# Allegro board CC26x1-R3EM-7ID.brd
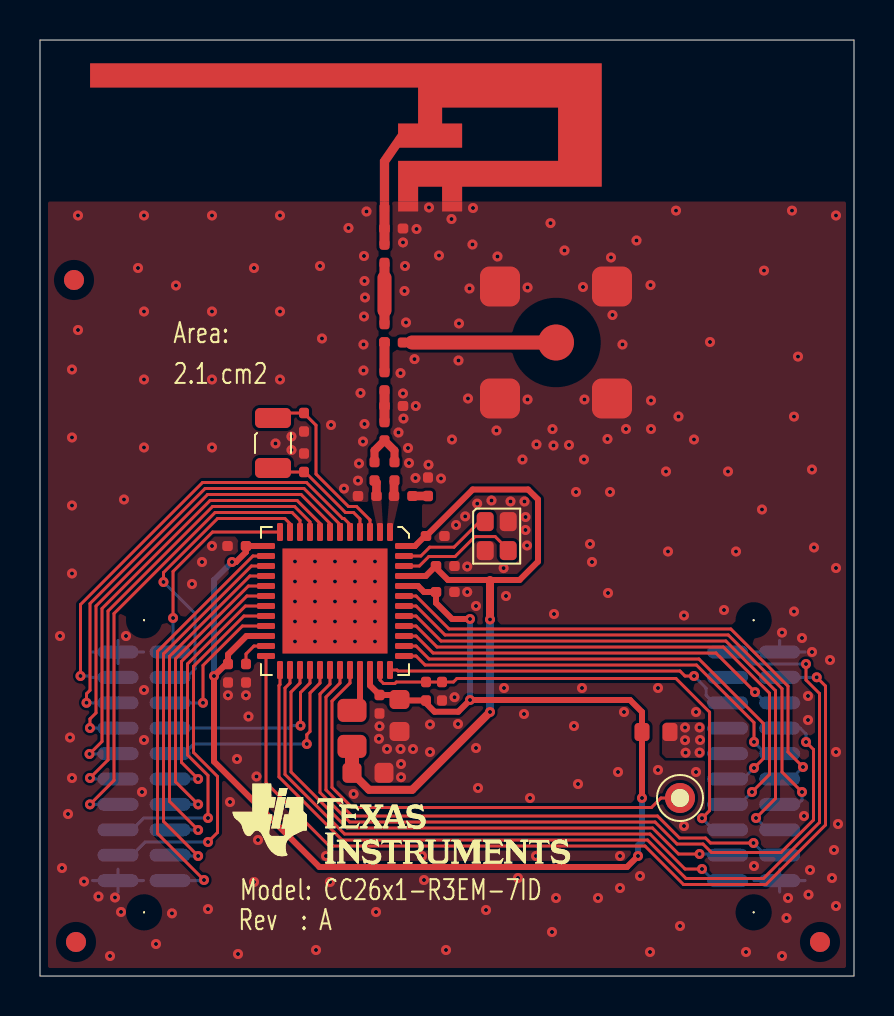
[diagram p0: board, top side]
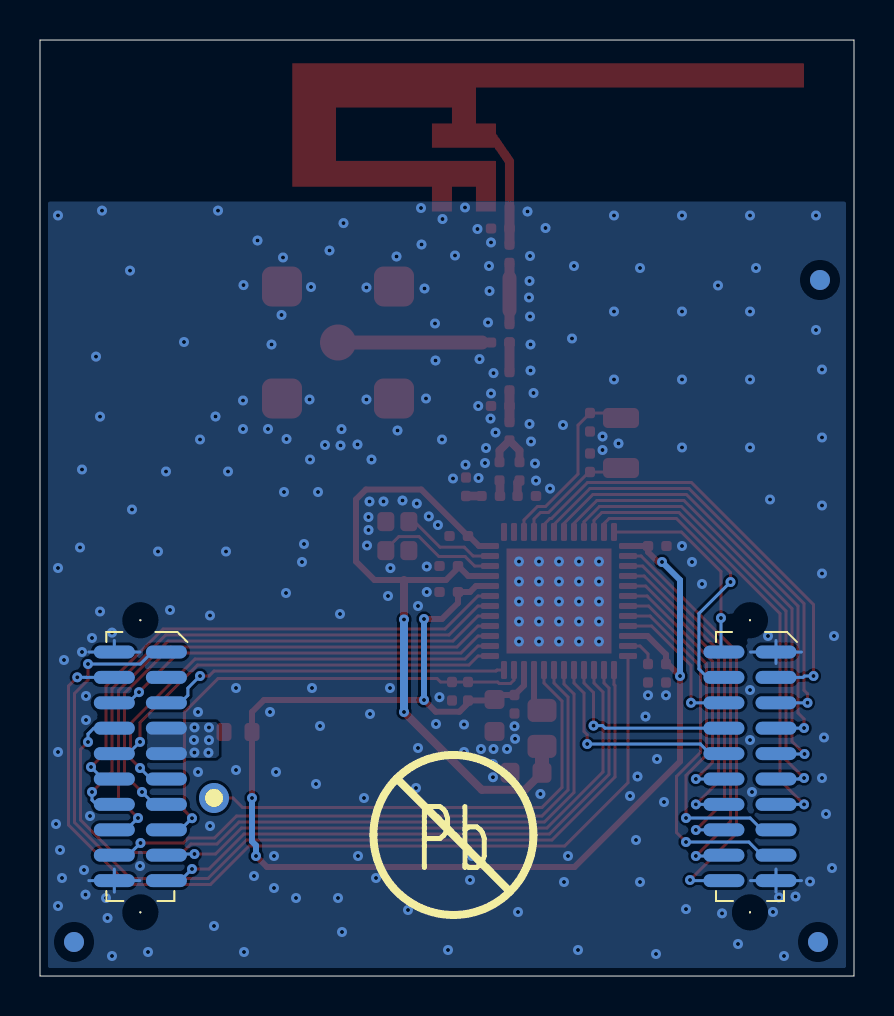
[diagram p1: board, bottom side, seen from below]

Outline 40.7 x 46.8 mm; copper layers: TOP, BOTTOM. Coordinates in mm from the lower left corner of the outline.
Outline path: 0,46.8 0,0 40.7,0 40.7,46.8 0,46.8

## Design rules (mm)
constraint set DEFAULT: min track width 0.15

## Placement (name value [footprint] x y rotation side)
A1  2.4GHz  [ANTENNA_DN007AN]  17.23 38.48 0 top
C3  0.1uF  [CAPC1005X60B2N]  10.3 21.5 180 top
C4  0.1uF  [CAPC1005X60B2N]  9.4 15.6 270 top
C5  0.1uF  [CAPC1005X60B2N]  19.8 19.2 0 top
C6  22uF  [CAPC1608X100A2N]  17.98 13.83 270 top
C7  0.1uF  [CAPC1005X60B2N]  16.98 14.05 270 top
C8  22uF  [CAPC1608X100A2N]  15.6 10.16 0 top
C9  0.1uF  [CAPC1005X60B2N]  19.8 20.5 0 top
C11  1pF  [CAPC1005X60B2N]  17.73 24.78 90 top
C13  1pF  [CAPC1005X60B2N]  18.15 28.5 180 top
C14  12pF  [CAPC1005X60B2N]  17.23 31.67 90 top
C15  DNM_0402  [CAPC1005X60B2N]  17.23 37.38 0 top
C16  0.1uF  [CAPC1005X60B2N]  19.3 22 0 top
C17  12pF  [CAPC1005X60B2N]  13.2 28.15 270 top
C18  12pF  [CAPC1005X60B2N]  13.2 25.2 90 top
C19  1uF  [CAPC1005X60B2N]  10.3 15.6 270 top
C20  0.1uF  [CAPC1005X60B2N]  20.1 14.7 270 top
C21  1pF  [CAPC1005X60B2N]  15.9 24 0 top
C24  12pF  [CAPC1005X60B2N]  18.15 31.67 180 top
C31  12pF  [CAPC1005X60B2N]  19.4 24 90 top
DIO22  TP_CIR_1.5mm_HOLE_0.9mm  [TP150_90H]  32 8.9 0 top
FIDU1  FIDU_1MM  [FID100X115B]  1.8 1.7 0 top
FIDU2  FIDU_1MM  [FID100X115B]  39 1.7 0 top
FIDU3  FIDU_1MM  [FID100X115B]  1.7 34.8 0 top
FIDU4  FIDU_1MM  [FID100X115B]  1.8 1.7 180 bottom
FIDU5  FIDU_1MM  [FID100X115B]  39 1.7 180 bottom
FIDU6  FIDU_1MM  [FID100X115B]  1.7 34.8 180 bottom
FL1  BLM18HE152SN1  [FIL_BLM18HE152SN1DN]  30.1 12.2 0 top
J1  SMA-10V21-TGG  [HUSTSAN_SMA10V21TGGAN]  25.8 31.67 0 top
L1  6.8uH  [INDC2012X150A2N]  15.6 13.28 270 top
L11  2.4nH  [INDC1005X60D2N]  17.7 24 0 top
L12  2nH  [INDC1005X60D2N]  17.23 26.78 90 top
L13  2nH  [INDC1005X60D2N]  17.23 29.28 90 top
L21  2.4nH  [INDC1005X60D2N]  16.73 24.78 90 top
LBL1  NON_COMPONENT_LABEL_8mm  [LABEL_PB-FREE_8MM_A2N]  24.24 2.84 180 bottom
LBL2  TI_LOGO  [TI_LOGO_1]  10.62 9.62 0 top
NOREF  -  []  0 40.29 0 top
NOREF#2  -  []  29.02 0 90 top
P1  SFM-110-02-S-D-A-K  [SAMTEC_SFM11002AN]  3.9 16.2 0 bottom
P2  SFM-110-02-S-D-A-K  [SAMTEC_SFM11002AN]  34.38 16.2 0 bottom
R1  100k  [RESC1005X40B2N]  19.3 14.7 270 top
R12  0  [RESC1005X40B2N]  17.23 36.58 270 top
U1  CC2651R31T0RGZR  [QFNFC50P700X700X100-49A2N]  17.5 22.2 180 top
Y1  32.768kHz  [XTAL_TZ1166C_A2N]  11.65 27.9 270 top
Y2  48MHz  [OSCCC200X160X50-4A2N]  22.26 22.72 270 top

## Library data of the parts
A1 = ANTENNA_DN007
C3-C5 C7 C9 C11 C13 C14 C16-C21 C24 C31 = CAPACITOR: User Part Number: #PN
C6 C8 = CAPACITOR: User Part Number: #PN; alternate symbols: (CAPC1608X100A2L,CAPC1608X100A2M)
C15 = CAPACITOR_CAPC1005X60B2N_DISC_2: User Part Number: #PN
DIO22 = TEST_POINT
FIDU1-FIDU6 = FIDMARK
FL1 = FILTER_2PIN: alternate symbols: (FIL_BLM18HE152SN1DL,FIL_BLM18HE152SN1DM)
J1 = CONN_COAX_1+4: alternate symbols: (HUSTSAN_SMA10V21TGGL,HUSTSAN_SMA10V21TGGM)
L1 = INDUCTOR: User Part Number: #PN; alternate symbols: (INDC2012X150A2L,INDC2012X150A2M)
L11-L13 L21 = INDUCTOR_HOR_1_2: User Part Number: #PN
LBL1 = LABEL_Pb-free_V1: User Part Number: #PN
LBL2 = TI_LOGO_V1
P1 P2 = CONN_HEADER_2X10_P_S: alternate symbols: (SAMTEC_SFM11002AL,SAMTEC_SFM11002AM)
R1 R12 = RESISTOR: User Part Number: #PN
U1 = IC_RF_CC2651R1F32_VQFN48: User Part Number: #PN; alternate symbols: (QFNFC50P700X700X100-49A2L,QFNFC50P700X700X100-49A2M)
Y1 = XTAL: User Part Number: #PN; alternate symbols: (XTAL_TZ1166C_A2L,XTAL_TZ1166C_A2M)
Y2 = XTAL_4_V3: User Part Number: #PN; alternate symbols: (OSCCC200X160X50-4A2L,OSCCC200X160X50-4A2M)

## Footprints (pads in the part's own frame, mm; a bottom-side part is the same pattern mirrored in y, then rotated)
ANTENNA_DN007AN
  rect 0.46x0.5 smd: 1(0,0)
  rect 1x0.5 smd: 2(1.18,0) 3(3.38,0)
CAPC1005X60B2N
  custom 0.125x0.125 smd: 1(0,0) 2(0.924,0)
CAPC1608X100A2N
  custom 0.237x0.237 smd: 1(0,0) 2(1.6,0)
FID100X115B
  round 1 smd: 1(0,0)
FIL_BLM18HE152SN1DN
  custom 0.188x0.188 smd: 1(0,0) 2(1.4,0)
HUSTSAN_SMA10V21TGGAN
  round 1.801 smd: 1(0,0)
  custom 0.5x0.5 smd: 2(-2.8,-2.8) 3(2.8,-2.8) 4(2.8,2.8) 5(-2.8,2.8)
INDC1005X60D2N
  custom 0.125x0.125 smd: 1(0,0) 2(0.924,0)
INDC2012X150A2N
  custom 0.287x0.287 smd: 1(0,0) 2(1.8,0)
OSCCC200X160X50-4A2N
  custom 0.212x0.212 smd: 1(0,0) 2(1.45,0) 3(1.45,1.15) 4(0,1.15)
QFNFC50P700X700X100-49A2N
  custom 0.075x0.075 smd: 1(0,0) 2(0.5,0) 3(1,0) 4(1.5,0) 5(2,0) 6(2.5,0) 7(3,0) 8(3.5,0) 9(4,0) 10(4.5,0) 11(5,0) 12(5.5,0) 13(6.2,0.7) 14(6.2,1.2) 15(6.2,1.7) 16(6.2,2.2) 17(6.2,2.7) 18(6.2,3.2) 19(6.2,3.7) 20(6.2,4.2) 21(6.2,4.7) 22(6.2,5.2) 23(6.2,5.7) 24(6.2,6.2) 25(5.5,6.9) 26(5,6.9) 27(4.5,6.9) 28(4,6.9) 29(3.5,6.9) 30(3,6.9) 31(2.5,6.9) 32(2,6.9) 33(1.5,6.9) 34(1,6.9) 35(0.5,6.9) 36(0,6.9) 37(-0.7,6.2) 38(-0.7,5.7) 39(-0.7,5.2) 40(-0.7,4.7) 41(-0.7,4.2) 42(-0.7,3.7) 43(-0.7,3.2) 44(-0.7,2.7) 45(-0.7,2.2) 46(-0.7,1.7) 47(-0.7,1.2) 48(-0.7,0.7)
  rect 5.25x5.25 smd: 49(2.75,3.45)
RESC1005X40B2N
  custom 0.125x0.125 smd: 1(0,0) 2(0.924,0)
SAMTEC_SFM11002AN
  round 0.099 hole 1.501 unplated: (1.302,-1.588) (1.302,13.017)
  oval 2.05x0.65 smd: 1(0,0) 2(2.604,0) 3(0,1.27) 4(2.604,1.27) 5(0,2.54) 6(2.604,2.54) 7(0,3.81) 8(2.604,3.81) 9(0,5.08) 10(2.604,5.08) 11(0,6.35) 12(2.604,6.35) 13(0,7.62) 14(2.604,7.62) 15(0,8.89) 16(2.604,8.89) 17(0,10.16) 18(2.604,10.16) 19(0,11.43) 20(2.604,11.43)
TP150_90H
  round 1.5 hole 0.9: 1(0,0)
XTAL_TZ1166C_A2N
  custom 0.25x0.25 smd: 1(0,0) 2(2.5,0)

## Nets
GND: A1.2 A1.3(GND_3) C3.2 C4.2 C5.2 C6.2 C7.2 C8.2 C9.2 C13.1 C15.2 C16.2 C17.2 C18.2 C19.2 C20.2 C21.1 C31.2 J1.2 J1.3 J1.4 J1.5 P1.1 P1.19 P2.2 P2.20 U1.49 Y2.2 Y2.4(GND#4)
VDD_EB: FL1.2 P2.7 P2.9
VDDR: C8.1 C9.1 C16.1 L1.2 U1.45 U1.48
VDDS: C3.1 C4.1 C5.1 C6.1 C7.1 FL1.1 R1.2 U1.13 U1.22 U1.34 U1.44
DCDC_SW: L1.1 U1.33
DIO_0: P1.3 U1.5
DIO_1: P1.5 U1.6
DIO_2: P1.7 U1.7
DIO_3: P1.9 U1.8
DIO_4: P1.11 U1.9
DIO_5: P1.13 U1.10
DIO_6: P1.4 U1.11
DIO_7: P1.2 U1.12
DIO_8: P1.20 U1.14
DIO_9: P1.18 U1.15(DIO_9)
DIO_10: P1.16 U1.16
DIO_11: P1.14 U1.17
DIO_12: P1.12 U1.18
DIO_13: P1.15 U1.19
DIO_14: P1.17 U1.20
DIO_15: P1.6 U1.21
DIO_16 / JTAG TDO: P2.19 U1.26
DIO_17 / JTAG TDI: P2.17 U1.27
DIO_18: P1.8 U1.28
DIO_19: P1.10 U1.29
DIO_20: P2.8 U1.30
DIO_21: P2.18 U1.31
DIO_22: DIO22.1 U1.32
DIO_23: P2.5 U1.36
DIO_24: P2.10 U1.37
DIO_25: P2.11 U1.38
DIO_26: P2.6 U1.39
DIO_27: P2.13 U1.40
DIO_28: P2.16 U1.41
DIO_29: P2.14 U1.42
DIO_30: P2.12 U1.43
JTAG_TCK: P2.1 U1.25
JTAG_TMS: P2.4 U1.24
NRESET: C20.1 P2.15 R1.1 U1.35
N310466: U1.47 Y2.1
N310868: U1.46 Y2.3
N314427: C21.2 L21.1 U1.2
N314470: C11.1 L11.1 U1.1
N314514: C31.1 L11.2
N314764: C11.2 L12.1 L21.2
N315193: C13.2 L12.2 L13.1
N316022: A1.1 C15.1 R12.1
N316040: C24.1 J1.1
N316649: C19.1 U1.23
N316919: C17.1 U1.3 Y1.1
N316932: C18.1 U1.4 Y1.2
N334495: C14.1 C24.2 L13.2
N356130: C14.2 R12.2

Pads without a net: FIDU1 1; FIDU2 1; FIDU3 1; FIDU4 1; FIDU5 1; FIDU6 1; P2 3

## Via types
v1: diameter 0.5, hole 0.2, TOP to BOTTOM, 296 vias

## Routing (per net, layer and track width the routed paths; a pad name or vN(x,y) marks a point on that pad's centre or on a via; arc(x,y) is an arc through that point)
GND: length 14.3
  BOTTOM w0.15: P2.2 38.26,16.2 ; P2.2 36.98,16.78 ; P2.2 35.71,16.2 ; P1.1 3.9,16.78 ; P1.1 3.9,15.62 ; P1.1 5.18,16.2 ; P1.1 2.62,16.2 ; 36.98,4.19 P2.20 ; P2.20 38.26,4.77 ; P2.20 35.71,4.77 ; P2.20 36.98,5.35 ; P1.19 3.9,5.35 ; P1.19 3.9,4.19 ; P1.19 5.18,4.77 ; P1.19 2.62,4.77
  vias: v1(1,17) v1(1.1,5.4) v1(1.4,8.1) v1(1.5,11.92) v1(1.6,30.33) v1(1.6,26.92) v1(1.6,23.53) v1(1.6,20.12) v1(1.6,9.9) v1(1.9,38.02) v1(1.9,32.3) v1(2.2,4.73) v1(2.93,3.98) v1(3.5,1) v1(3.75,3.92) v1(4.05,3.2) v1(4.2,23.83) v1(4.3,17) v1(4.9,35.4) v1(5.1,9.2) v1(5.2,38.02) v1(5.2,33.23) v1(5.2,29.83) v1(5.2,26.42) v1(5.2,14.3) v1(5.2,11.8) v1(5.8,1.6) v1(6.6,3.13) v1(6.8,34.52) v1(7.6,19.6) v1(8.1,20.7) v1(8.4,3.34) v1(8.6,38.02) v1(8.6,33.23) v1(8.6,29.83) v1(8.6,26.42) v1(8.6,21.5) v1(9.4,14.04) v1(9.5,8.7) v1(9.85,10.85) v1(9.9,1.1) v1(10.3,14.04) v1(10.43,12.98) v1(10.7,35.4) v1(10.7,4.7) v1(10.83,9.98) v1(10.9,6.8) v1(11.2,9) v1(11.78,26.62) v1(12,38.02) v1(12,33.23) v1(12,29.83) v1(12.57,26.98) v1(12.58,26.3) v1(12.75,20.73) v1(12.75,19.73) v1(12.75,18.73) v1(12.75,17.73) v1(12.75,16.73) v1(13.75,20.73) v1(13.75,19.73) v1(13.75,18.73) v1(13.75,17.73) v1(13.75,16.73) v1(13.8,1.3) v1(14,35.5) v1(14.1,31.88) v1(14.3,6) v1(14.5,4.7) v1(14.55,27.55) v1(14.75,20.73) v1(14.75,19.73) v1(14.75,18.73) v1(14.75,17.73) v1(14.75,16.73) v1(15.2,24.37) v1(15.43,37.4) v1(15.75,20.73) v1(15.75,19.73) v1(15.75,18.73) v1(15.75,17.73) v1(15.75,16.73) v1(15.68,9.1) v1(15.95,25.62) v1(15.9,24.77) v1(16.03,29.15) v1(16.15,26.73) v1(16.2,36) v1(16.23,34.75) v1(16.25,33.92) v1(16.2,32.98) v1(16.18,31.58) v1(16.18,30.28) v1(16.23,27.6) v1(16.33,38.23) v1(16.75,20.73) v1(16.75,19.73) v1(16.75,18.73) v1(16.75,17.73) v1(16.75,16.73) v1(16.8,3.2) v1(16.95,11.86) v1(16.98,12.49) v1(17.35,11.35) v1(17.93,27.17) v1(18.03,30.14) v1(18.03,11.35) v1(18.15,36.68) v1(18.15,29.13) v1(18.05,10.6) v1(18.05,9.94) v1(18.25,35.5) v1(18.23,34.25) v1(18.18,27.87) v1(18.3,32.67) v1(18.4,26.4) v1(18.45,25.65) v1(18.73,30.84) v1(18.65,11.35) v1(18.83,37.35) v1(18.79,28.5) v1(18.77,24.9) v1(19.1,6) v1(19.2,4.8) v1(19.45,38.42) v1(19.43,25.56) v1(19.5,12.58) v1(19.5,11.2) v1(19.95,36.02) v1(20.05,24.88) v1(20.3,1.3) v1(20.58,37.85) v1(20.6,26.83) v1(20.73,13.94) v1(20.8,22.55) v1(20.95,32.62) v1(20.93,30.78) v1(20.9,12.6) v1(21.26,22.98) v1(21.4,28.88) v1(21.36,20.48) v1(21.36,19.2) v1(21.48,34.38) v1(21.62,36.58) v1(21.65,38.4) v1(21.8,18.5) v1(21.8,11.4) v1(21.86,23.62) v1(21.9,9.4) v1(22.3,3.3) v1(22.58,23.78) v1(22.83,27.28) v1(22.88,35.98) v1(23.18,20.39) v1(23.2,14.4) v1(23.3,19) v1(23.53,23.73) v1(23.9,4.9) v1(24.12,25.83) v1(24.22,23.73) v1(24.2,13.1) v1(24.28,22.95) v1(24.28,22.3) v1(24.35,21.53) v1(24.38,34.42) v1(24.38,28.83) v1(24.5,8.9) v1(24.83,26.58) v1(24.8,6) v1(25.53,37.64) v1(25.62,27.34) v1(25.6,2.2) v1(25.68,26.53) v1(25.7,18.1) v1(25.8,3.9) v1(26.22,36.27) v1(26.45,26.55) v1(26.7,12.5) v1(26.8,24.2) v1(26.9,9.6) v1(27.15,34.45) v1(27.1,14.4) v1(27.22,28.83) v1(27.2,25.83) v1(27.5,21.6) v1(27.6,20.7) v1(27.9,3.9) v1(28.38,26.85) v1(28.4,19.15) v1(28.5,24.2) v1(28.55,35.92) v1(28.62,33.05) v1(28.9,10.2) v1(29,6) v1(29,4.4) v1(29.12,31.58) v1(29.2,13.2) v1(29.3,27.35) v1(29.83,36.77) v1(30,5) v1(30.53,34.55) v1(30.5,1.2) v1(30.55,28.78) v1(30.55,27.35) v1(30.9,14.4) v1(30.9,10.3) v1(31.3,25.23) v1(31.4,21.23) v1(31.8,38.27) v1(31.93,27.98) v1(32,2.5) v1(32.2,18.03) v1(32.2,7.5) v1(32.7,26.83) v1(32.8,13.2) v1(32.8,10.2) v1(33.5,31.7) v1(34.2,18.3) v1(34.4,25.23) v1(34.8,21.23) v1(35.3,1.2) v1(35.7,5.5) v1(36.1,23.33) v1(36.2,35.27) v1(37.1,17.17) v1(37.1,1) v1(37.33,2.9) v1(37.4,3.9) v1(37.6,38.27) v1(37.7,27.97) v1(37.7,18.23) v1(37.9,30.97) v1(38.1,16.9) v1(38.2,8) v1(38.4,14) v1(38.4,12.8) v1(38.43,4.07) v1(38.5,5.3) v1(38.6,25.33) v1(38.6,16.2) v1(38.7,21.42) v1(39.5,15.8) v1(39.6,4.9) v1(39.7,6.3) v1(39.8,38.02) v1(39.8,20.4) v1(39.8,11.2) v1(39.8,3.5) v1(39.9,7.6)
VDD_EB:
  vias: v1(32.25,12.42) v1(32.25,11.79) v1(32.28,11.17) v1(32.98,12.43) v1(33,11.8) v1(32.98,11.17)
VDDR: length 35.6
  TOP w0.3: U1.45 19.29,20 19.79,20.5 C9.1 19.8,20.4 20.4,19.8 23.98,19.8 24.9,20.72 24.9,23.83 24.4,24.33 21.64,24.33 19.31,22 C16.1 19.25,22 18.75,21.5 U1.48
  TOP w0.4: 22.5,19.8 v1(22.5,17.83) ; C8.1 16.45,9.31 18.61,9.31 v1(22.5,13.2)
  TOP w0.7: L1.2 C8.1
  BOTTOM w0.4: v1(22.5,13.2) v1(22.5,17.83)
VDDS: length 71
  TOP w0.3: U1.22 10.32,17 9.4,16.08 C4.1 9.3,15.6 v1(8.7,15) 8.7,10.72 13.97,5.45 29.35,5.45 v1(29.9,6) ; U1.13 C3.1 10.3,21.2 9.8,20.7 v1(9.6,20.7) ; v1(21.5,17.85) 20.6,17.85 19.8,18.65 C5.1 19.2,19.2 18.9,19.5 U1.44 ; U1.34 16.5,14.53 C7.1 17.75,14.05 C6.1 18.02,13.78 R1.2 19.3,13.64 19.73,13.21 20.91,13.21 v1(21.5,13.8) 29.5,13.8 30.1,13.2 FL1.1 v1(30.1,8.9)
  BOTTOM w0.3: v1(29.9,6) 29.9,6.53 30.1,6.73 v1(30.1,8.9) ; v1(21.5,13.8) v1(21.5,17.85) ; v1(8.7,15) 8.7,19.8 v1(9.6,20.7)
DCDC_SW: length 2.2
  TOP w0.3: L1.1 16,13.68 U1.33
DIO_0: length 22.7
  TOP w0.15: v1(2.03,15) 2.03,18.57 8.13,24.67 13.33,24.67 15.12,22.88 15.2,22.88 15.5,22.58 U1.5
  BOTTOM w0.15: P1.3 2.55,14.93 2.48,15 v1(2.03,15)
DIO_1: length 22.6
  TOP w0.15: U1.6 15,22.58 13.2,24.38 8.25,24.38 2.5,18.62 2.5,14.29 2.33,14.11 v1(2.33,13.66)
  BOTTOM w0.15: v1(2.33,13.66) P1.5
DIO_2: length 22.7
  TOP w0.15: v1(2.5,12.4) 2.5,12.85 2.8,13.15 2.8,18.5 8.38,24.08 13.06,24.08 14.5,22.63 U1.7
  BOTTOM w0.15: P1.7 2.71,12.39 2.7,12.4 v1(2.5,12.4)
DIO_3: length 23
  TOP w0.15: U1.8 14,22.63 12.86,23.78 8.5,23.78 3.1,18.37 3.1,11.73 v1(2.48,11.1)
  BOTTOM w0.15: P1.9 3.88,11.1 v1(2.48,11.1)
DIO_4: length 23.2
  TOP w0.15: U1.9 13.5,22.71 12.73,23.48 8.63,23.48 3.4,18.25 3.4,10.8 v1(2.5,9.9)
  BOTTOM w0.15: P1.11 2.75,9.85 2.7,9.9 v1(2.5,9.9)
DIO_5: length 23.6
  TOP w0.15: U1.10 13,22.78 12.61,23.17 8.75,23.17 3.7,18.12 3.7,9.78 v1(2.5,8.58)
  BOTTOM w0.15: P1.13 v1(2.5,8.58)
DIO_6: length 14.9
  TOP w0.15: v1(6.18,19.7) 6.18,20.17 8.88,22.88 12.24,22.88 12.5,22.62 U1.11
  BOTTOM w0.15: P1.4 7.33,14.93 7.75,15.35 7.75,18.12 v1(6.18,19.7)
DIO_7: length 10.3
  TOP w0.15: v1(6.65,17.9) 6.65,20.23 8.63,22.2 U1.12
  BOTTOM w0.15: P1.2 6.65,16.35 6.65,17.9 v1(6.65,17.9)
DIO_8: length 21.5
  TOP w0.15: v1(8.2,4.8) 5.88,7.12 5.88,16.23 10.64,21 U1.14
  BOTTOM w0.15: v1(8.2,4.8) 8.17,4.77 P1.20
DIO_9: length 19.2
  TOP w0.15: U1.15 10.57,20.5 6.18,16.11 6.18,7.73 v1(7.91,6)
  BOTTOM w0.15: v1(7.91,6) 6.54,6 P1.18
DIO_10: length 17.2
  TOP w0.15: v1(7.91,7.3) 6.48,8.73 6.48,15.98 10.49,20 U1.16
  BOTTOM w0.15: P1.16 7.73,7.31 7.74,7.3 v1(7.91,7.3)
DIO_11: length 15.2
  TOP w0.15: v1(7.91,8.58) 6.78,9.71 6.78,15.86 10.42,19.5 U1.17
  BOTTOM w0.15: v1(7.91,8.58) P1.14
DIO_12: length 13.2
  TOP w0.15: U1.18 10.34,19 7.08,15.73 7.08,10.68 v1(7.91,9.85)
  BOTTOM w0.15: v1(7.91,9.85) P1.12
DIO_13: length 18
  TOP w0.15: v1(8.4,7.9) 8.4,10.03 7.38,11.05 7.38,15.61 10.27,18.5 U1.19
  BOTTOM w0.15: P1.15 4.6,7.31 5.19,7.9 v1(8.4,7.9)
DIO_14: length 18.9
  TOP w0.15: U1.20 10.2,18 7.68,15.48 7.68,11.18 8.88,9.98 8.88,7.17 v1(8.4,6.7)
  BOTTOM w0.15: P1.17 4.6,6.04 5.26,6.7 v1(8.4,6.7)
DIO_15: length 7.5
  TOP w0.15: U1.21 10.12,17.5 8.15,15.53 v1(8.15,13.66)
  BOTTOM w0.15: P1.6 v1(8.15,13.66)
DIO_16 / JTAG TDO: length 29.7
  TOP w0.15: U1.26 12.5,14.65 12.25,14.4 12.25,10.08 15.23,7.1 30.5,7.1 32.25,5.35 v1(33.1,5.35)
  BOTTOM w0.15: v1(33.1,5.35) 33.68,4.77 P2.19
DIO_17 / JTAG TDI: length 28.8
  TOP w0.15: U1.27 13,14.65 12.55,14.2 12.55,10.2 15.35,7.4 30.62,7.4 31.93,6.1 v1(32.98,6.1)
  BOTTOM w0.15: P2.17 33.68,6.04 33.62,6.1 v1(32.98,6.1)
DIO_18: length 9.6
  TOP w0.15: U1.28 13.5,14.65 13.03,14.17 v1(13.03,12.52)
  BOTTOM w0.15: v1(13.03,12.52) 12.57,12.52 12.45,12.39 P1.8
DIO_19: length 11
  TOP w0.15: U1.29 14,14.65 13.5,14.15 13.5,12.23 13.34,12.07 v1(13.34,11.6)
  BOTTOM w0.15: P1.10 7.2,11.12 7.68,11.6 v1(13.34,11.6)
DIO_20: length 38.8
  TOP w0.15: v1(38.3,11.7) 38.68,11.33 38.68,7.8 37.05,6.17 33.58,6.17 33.15,6.6 31.85,6.6 30.75,7.7 15.48,7.7 14,9.18 14,14.1 14.5,14.6 U1.30
  BOTTOM w0.15: P2.8 38.01,12.39 38.3,12.1 v1(38.3,11.7)
DIO_21: length 30.3
  TOP w0.15: U1.31 15,14.65 14.3,13.95 14.3,9.3 15.6,8 30.88,8 31.97,6.9 33.28,6.9 33.53,6.65 v1(35.67,6.65)
  BOTTOM w0.15: P2.18 36.28,6.04 v1(35.67,6.65)
DIO_22: length 24.3
  TOP w0.15: DIO22.1 31.05,8.9 30.57,8.42 15.6,8.42 14.6,9.43 14.6,13.75 15.5,14.65 U1.32
DIO_23: length 17.8
  TOP w0.15: U1.36 17.85,15.3 17.9,15.25 32,15.25 32.25,15 v1(32.7,15)
  BOTTOM w0.15: v1(32.7,15) 33.31,14.39 33.31,14.03 33.68,13.66 P2.5
DIO_24: length 21.4
  TOP w0.15: U1.37 18.8,16 19.25,15.55 32.82,15.55 35.7,12.67 v1(35.7,11.7)
  BOTTOM w0.15: v1(35.7,11.7) 36.28,11.12 P2.10
DIO_25: length 23.5
  TOP w0.15: v1(35.7,10.4) 36.18,10.88 36.18,12.62 32.95,15.85 19.45,15.85 18.8,16.5 U1.38
  BOTTOM w0.15: P2.11 35.15,9.85 v1(35.7,10.4)
DIO_26: length 20.2
  TOP w0.15: U1.39 18.8,17 19.65,16.15 33.79,16.15 v1(35.75,14.19)
  BOTTOM w0.15: v1(35.75,14.19) 36.28,13.66 P2.6
DIO_27: length 26.4
  TOP w0.15: v1(35.6,9.2) 36.47,10.08 36.47,14.14 34.17,16.45 19.85,16.45 18.8,17.5 U1.40
  BOTTOM w0.15: v1(35.6,9.2) 34.98,8.58 P2.13
DIO_28: length 28.3
  TOP w0.15: v1(35.8,7.9) 36.78,8.88 36.78,14.27 34.29,16.75 20.05,16.75 18.8,18 U1.41
  BOTTOM w0.15: P2.16 36.97,7.3 36.4,7.3 v1(35.8,7.9)
DIO_29: length 27.8
  TOP w0.15: v1(38.1,9.2) 37.1,10.2 37.1,14.37 34.41,17.05 20.25,17.05 18.8,18.5 U1.42
  BOTTOM w0.15: v1(38.1,9.2) 38.1,8.8 37.88,8.58 P2.14
DIO_30: length 26.8
  TOP w0.15: U1.43 18.8,19 20.45,17.35 34.54,17.35 37.4,14.49 37.4,11.2 v1(38.15,10.45)
  BOTTOM w0.15: P2.12 37.55,9.85 v1(38.15,10.45)
JTAG_TCK: length 48
  TOP w0.15: U1.25 12,14.57 11.95,14.52 11.95,9.95 15.1,6.8 30.38,6.8 32.3,4.88 36.17,4.88 38.97,7.68 38.97,14.12 38.3,14.8 v1(38.3,15.6)
  BOTTOM w0.15: P2.1 35.08,16.2 35.68,15.6 v1(38.3,15.6)
JTAG_TMS: length 47.1
  TOP w0.15: U1.24 11.3,9.67 14.47,6.5 30.25,6.5 32.18,4.58 36.3,4.58 39.28,7.55 39.28,14.5 v1(38.84,14.94)
  BOTTOM w0.15: P2.4 38.38,14.93 38.38,14.94 v1(38.84,14.94)
NRESET: length 24.8
  TOP w0.15: v1(33.1,7.89) 33.48,8.27 33.48,13.19 31.8,14.88 20.85,14.88 20.67,14.7 C20.1 R1.1 17.82,14.7 17.74,14.62 17.18,14.62 17,14.8 U1.35
  BOTTOM w0.15: v1(33.1,7.89) 33.68,7.31 P2.15
N310466: length 4.8
  TOP w0.15: Y2.1 21.98,22.72 20.7,21.44 19.48,21.44 19.04,21 U1.47
N310868: length 6.1
  TOP w0.15: Y2.3 23.41,21.32 22.76,21.97 21.75,21.97 20.76,20.98 19.44,20.98 18.97,20.5 U1.46
N314427: length 0.8
  TOP w0.43: C21.2 16.82,24.68 L21.1
N314470: length 0.8
  TOP w0.43: L11.1 17.7,24.75 C11.1
N314514: length 0.8
  TOP w0.43: C31.1 L11.2
N314764: length 2.6
  TOP w0.4: L21.2 16.73,26.28 L12.1 17.73,26.28 C11.2
N315193: length 1.6
  TOP w0.43: L13.1 17.23,29.27 ; 17.23,28.5 C13.2
  TOP w0.5: 17.23,29.27 C13.2 ; L12.2 17.23,28.5
N316022: length 1.9
  TOP w0.5: A1.1 C15.1 R12.1
N316040: length 7.7
  TOP w0.43: C24.1 18.6,31.67
  TOP w0.7: 18.6,31.67 J1.1
N316649: length 1.7
  TOP w0.15: U1.23 10.7,16.5 10.3,16.1 C19.1
N316919: length 9.2
  TOP w0.15: Y1.1 11.9,28.15 C17.1 13.2,28.14 13.8,27.54 13.8,25.1 15.42,23.48 15.83,23.48 16.5,22.8 U1.3
N316932: length 6.1
  TOP w0.15: Y1.2 11.85,25.2 C18.1 13.25,25.2 15.27,23.17 15.68,23.17 16,22.85 U1.4
N334495: length 1.5
  TOP w0.5: C14.1 L13.2
N356130: length 3.1
  TOP w0.5: C14.2 17.23,33.28 ; 17.23,34.91 R12.2
  TOP w0.7: 17.23,33.28 17.23,34.91

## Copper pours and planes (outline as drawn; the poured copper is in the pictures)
GND on TOP (solid shape): 28.09,39.46 21.11,39.46 21.11,38.73 20.11,38.73 20.11,39.46 18.91,39.46 18.91,38.73 17.91,38.73 17.91,40.76 25.91,40.76 25.91,43.42 20.11,43.42 20.11,42.63 21.11,42.63 21.11,41.42 17.98,41.42 17.46,40.66 17.46,38.73 17,38.73 17,40.8 17.91,42.12 17.91,42.63 18.91,42.63 18.91,44.42 2.51,44.42 2.51,45.64 28.09,45.64
GND on TOP: 0.4,0.4 0.4,38.73 16.85,38.73 16.85,38.05 17.6,38.05 17.6,38.73 40.3,38.73 40.3,0.4 ; 13 cut-outs
GND on BOTTOM: 0.4,0.4 0.4,38.73 40.3,38.73 40.3,0.4 ; 8 cut-outs
VDD_EB on TOP: 31.3,12.7 33.1,12.7 33.3,12.5 33.3,11.1 33.1,10.9 31.3,10.9 31.1,11.1 31.1,12.5
VDD_EB on BOTTOM: 31.9,12.7 35.1,12.7 35.35,12.45 35.35,11.05 35.2,10.9 31.9,10.9 31.75,11.03 31.75,12.55
N314427 on TOP: 16.57,24.2 16.58,23.75 16.85,22.45 16.85,22 17.15,22 17.15,22.45 17.08,23.75 17.08,24.2
N314470 on TOP: 17.95,24.2 17.95,23.75 17.65,22.45 17.65,22 17.35,22 17.35,22.45 17.45,23.75 17.44,24.2

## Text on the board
Ref Des/Silkscreen Top: Area: | 2.1 cm2 | Rev  : A | Model: CC26x1-R3EM-7ID
XSECTION_CHART: L1: TOP CONDUCTOR - COPPER 0.035 MM | *  DIELECTRIC - FR-4 0.73 MM | L2: BOTTOM CONDUCTOR - COPPER 0.035 MM | DESIGN CROSS SECTION CHART | ___________________________ | TOTAL THICKNESS 0.8 MM +/- 0.08 MM
User.5: FIGURE | FINISHED_SIZE | 0.2 | 0.9 | 1.501 | DRILL CHART: TOP to BOTTOM | ALL UNITS ARE IN MILLIMETERS | PLATED | NON-PLATED | QTY | 271 | 25 | 1 | 4
